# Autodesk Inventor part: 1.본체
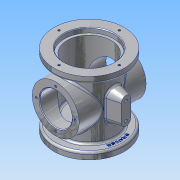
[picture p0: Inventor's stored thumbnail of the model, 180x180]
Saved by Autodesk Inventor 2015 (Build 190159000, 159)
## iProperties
Created: 2018-02
Part Number: 1.본체
Material: 알루미늄 6061
Document SubType Name: Modeling
Designer: user
Density: 2.7 g/cm^3
Appearance: 알루미늄 - 평지
Mass: 769.009 g
Surface Area: 821.625 cm^2
Volume: 284.818 cm^3
Author: user
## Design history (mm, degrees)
sketch "스케치9"
  geometry: C1 r 38 at (0, 0); 1 further point
  constraints: 1 centre point, 1 coincident
  dimensions: "d26" = 76 diameter of C1
extrude "돌출9" new body sketch "스케치9" stored distance "d27" = 88; taper "d28" = 0 deg
sketch "스케치10"
  geometry: C1 r 38 at (0, 0) reference; C2 r 52.5 at (0, 0)
  constraints: 1 centre point, 1 coincident
  dimensions: "d29" = 105 diameter of C2
extrude "돌출10" join sketch "스케치10" distance "d30" = 10; taper "d31" = 0 deg
sketch "스케치11"
  geometry: C1 r 38 at (0, 0) reference; C2 r 52.5 at (0, 0)
  constraints: 1 centre point, 1 coincident
  dimensions: "d32" = 105 diameter of C2
extrude "돌출11" join sketch "스케치11" distance "d33" = 10; taper "d34" = 0 deg
sketch "스케치12"
  geometry: L1 (-52.5, -54)-(52.5, -54) reference; L2 (38, -44)-(38, 44) reference; C1 r 35 at (0, 0); 3 further points
  constraints: 2 midpoint, 1 centre point, 1 coincident, 1 horizontal alignment, 1 vertical alignment
  dimensions: "d37" = 70 diameter of C1
extrude "돌출12" join sketch "스케치12" stored distance "d38" = 100; taper "d39" = 0 deg
sketch "스케치13"
  geometry: C1 r 52.5 at (0, 0) reference; C2 r 37 at (0, 0)
  constraints: 1 centre point, 1 coincident
  dimensions: "d40" = 74 diameter of C2
extrude "돌출13" cut sketch "스케치13" distance "d41" = 7; taper "d42" = 0 deg
sketch "스케치14"
  geometry: C1 r 37 at (0, 0) reference; C2 r 33 at (0, 0)
  constraints: 1 centre point, 1 coincident
  dimensions: "d43" = 66 diameter of C2
extrude "돌출14" cut sketch "스케치14" distance "d44" = 79; taper "d45" = 0 deg
sketch "스케치15"
  geometry: C1 r 52.5 at (0, 0) reference; C2 r 34 at (0, 0)
  constraints: 1 centre point, 1 coincident
  dimensions: "d46" = 68 diameter of C2
extrude "돌출15" cut sketch "스케치15" distance "d47" = 16; taper "d48" = 0 deg
sketch "스케치16"
  geometry: C1 r 34 at (0, 0) reference; C2 r 5 at (0, 0)
  constraints: 1 centre point, 1 coincident
  dimensions: "d49" = 10 diameter of C2
extrude "돌출16" cut sketch "스케치16" stored distance "d50" = 16; taper "d51" = 0 deg
sketch "스케치17"
  geometry: C1 r 37 at (0, 0) reference; 1 further point
  constraints: 1 vertical alignment
  dimensions: "d52" = 45 distance of C1.centre point (0, 45)
hole "구멍1" sketch "스케치17" at (0, 45) diameter "d53" = 3.242; stored, may be unused: countersink angle "d57" = 90 deg, drill point angle "d59" = 118 deg; dims "d54" = 4, "d55" = 4, "d56" = 2, "d58" = 6
sketch "스케치18"
  geometry: C1 r 35 at (0, 0) reference; C2 r 24 at (0, 0)
  constraints: 1 centre point, 1 coincident
  dimensions: "d63" = 48 diameter of C2
extrude "돌출17" cut sketch "스케치18" stored distance "d64" = 16; taper "d65" = 0 deg
sketch "스케치19"
  geometry: C1 r 24 at (0, 0) reference; 1 further point
  constraints: 1 vertical alignment
  dimensions: "d66" = 29 distance of C1.centre point (0, 29)
hole "구멍2" sketch "스케치19" at (0, 29) diameter "d67" = 3.242; stored, may be unused: countersink angle "d71" = 90 deg, drill point angle "d73" = 118 deg; dims "d68" = 4, "d69" = 4, "d70" = 2, "d72" = 6
node "작업 평면1"
chamfer "모따기1" distance "d91" = 1; stored, may be unused: second distance "d92" = 2, angle "d93" = 45 deg
chamfer "모따기2" distance "d94" = 1; stored, may be unused: second distance "d95" = 2, angle "d96" = 45 deg
chamfer "모따기3" distance "d97" = 1; stored, may be unused: second distance "d98" = 2, angle "d99" = 45 deg
fillet "모깎기1" dims "d100" = 3
fillet "모깎기2" dims "d101" = 3
fillet "모깎기3" dims "d102" = 3
sketch "스케치24"
  geometry: C1 r 49.5 at (0, 0) reference; C2 r 43 at (0, 0)
  constraints: 1 centre point, 1 coincident, 1 other
  dimensions: "d109" = 86 diameter of C2
feature "엠보싱2" sketch "스케치24" dims "d110" = 0.4, "d111" = 0
node "작업 평면2"
sketch "스케치25"
  geometry: L1 (0, -13)-(0, 13); L2 (7, -13)-(7, 13); L3 (-7, 13)-(-7, -13); A1 r 7 centre (0, -13) between (-7, -13) and (7, -13); A2 r 7 centre (0, 13) between (7, 13) and (-7, 13); 1 further point
  constraints: 8 end point, 4 point on circle, 4 tangent, 2 centre point, 1 midpoint, 1 parallel, 1 vertical
  dimensions: "d115" = 7 radius of A2; "d118" = 40 dimension on A1 A2
extrude "돌출19" join sketch "스케치25" stored distance "d116" = 16; taper "d117" = 15 deg
fillet "모깎기5" dims "d119" = 3
sketch "스케치27"
  geometry: A1 r 7 centre (-13, 0) between (-13, 7) and (-13, -7) reference; A2 r 7 centre (13, 0) between (13, -7) and (13, 7) reference; 3 further points
  constraints: 2 coincident
hole "구멍4" sketch "스케치27" at (13, 0), (-13, 0) diameter "d120" = 4.134; stored, may be unused: countersink angle "d124" = 90 deg, drill point angle "d126" = 118 deg; dims "d121" = 6, "d122" = 4, "d123" = 2, "d125" = 8
fillet "모깎기6" dims "d127" = 3
fillet "모깎기7" dims "d128" = 3
node "솔리드2"
pattern_circular "원형 패턴1" dims angle "d61" = 360 deg
pattern_circular "원형 패턴2" dims angle "d75" = 360 deg
mirror "대칭1"
other parameters: "d77" = 55, "d112" = -55
